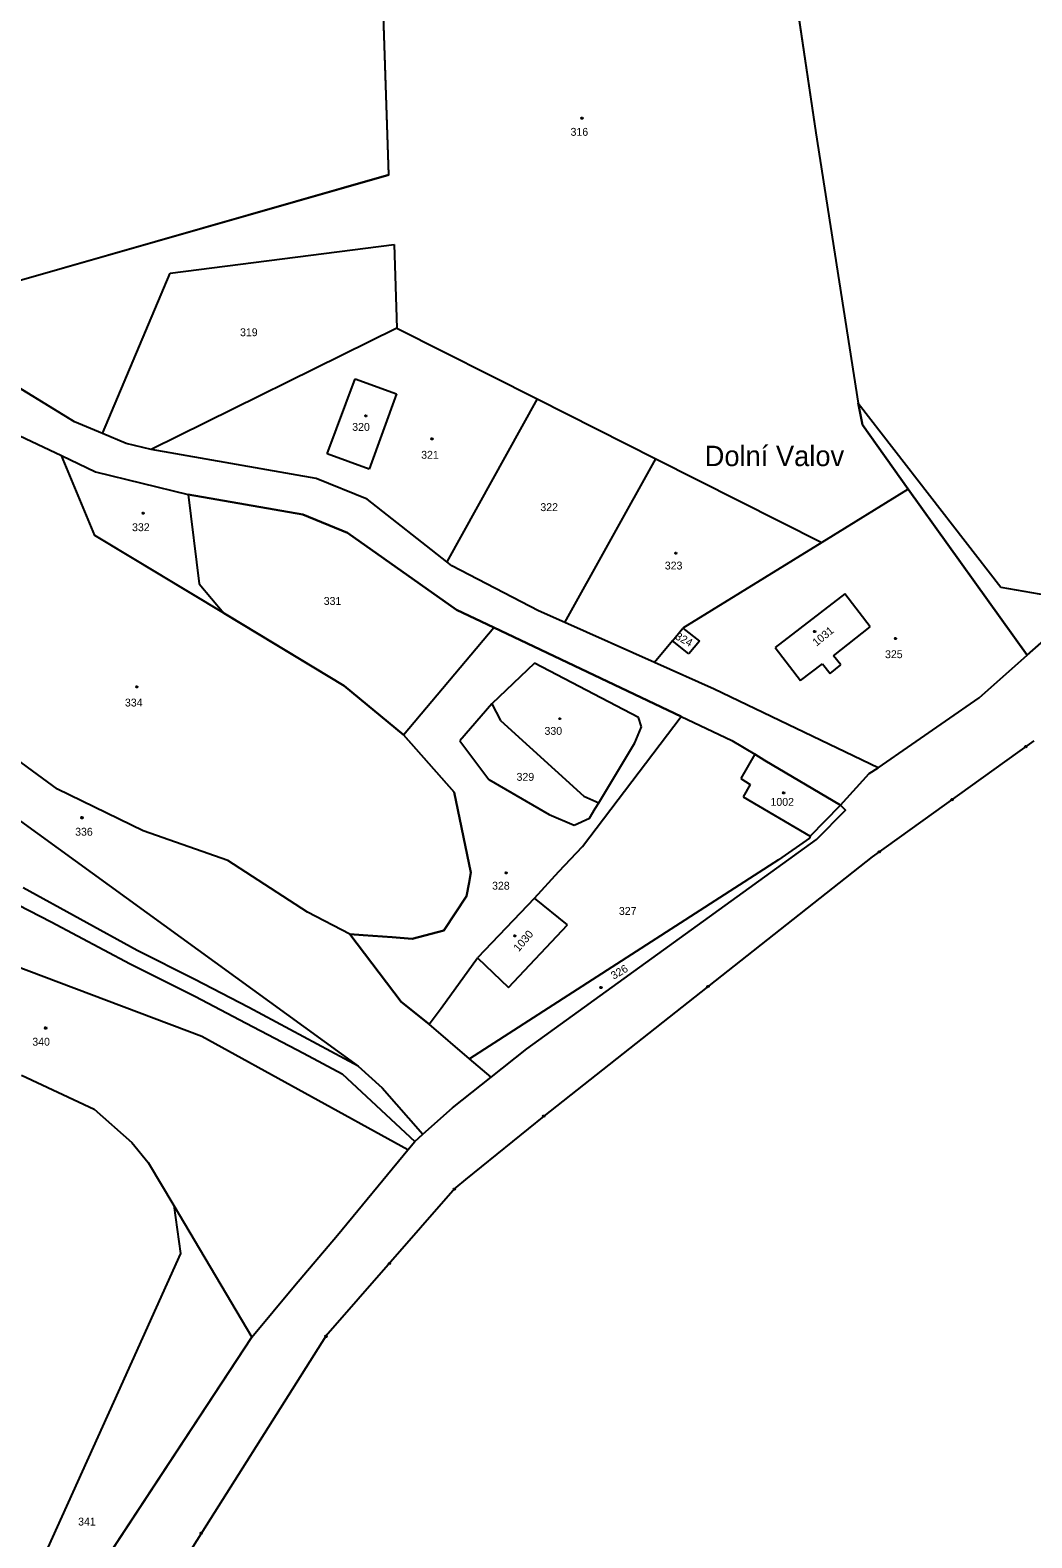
# Model space of a CAD drawing. Extents: x -841286 to -834997, y -1020681 to -1017810.
# Drawn here: x -835974.1 to -835758, y -1019779.8 to -1019454.5 of the extents above; entities that cross this region are included whole.
import ezdxf

# ---------------------------------------------------------------- set-up
doc = ezdxf.new("R2010")
doc.units = 0
for name, color, linetype in [('NERES_HRA', 7, 'Continuous'), ('NERES_SET', 7, 'Continuous'), ('OVNE_POP', 7, 'Continuous'), ('OVNE_PRE', 7, 'Continuous'), ('OVNE_SET', 7, 'Continuous'), ('OVNI_PRE', 7, 'Continuous'), ('OVNI_SET', 7, 'Continuous')]:
    doc.layers.add(name, color=color, linetype=linetype)

msp = doc.modelspace()

# ---------------------------------------------------------------- linework, layer by layer
at = {"layer": 'NERES_HRA'}
for points in [[(-835863.21, -1019688.7), (-835863.12, -1019688.85), (-835863.21, -1019689), (-835863.39, -1019689), (-835863.48, -1019688.85), (-835863.39, -1019688.7)], [(-835910.17, -1019736.18), (-835910.08, -1019736.33), (-835910.17, -1019736.48), (-835910.35, -1019736.48), (-835910.44, -1019736.33), (-835910.35, -1019736.18)]]:
    msp.add_lwpolyline(points, close=True, dxfattribs=at)
at = {"layer": 'OVNE_POP'}
for points in [[(-835854.94, -1019473.37), (-835854.85, -1019473.52), (-835854.94, -1019473.67), (-835855.12, -1019473.67), (-835855.21, -1019473.52), (-835855.12, -1019473.37)], [(-835901.59, -1019537.59), (-835901.5, -1019537.74), (-835901.59, -1019537.89), (-835901.77, -1019537.89), (-835901.86, -1019537.74), (-835901.77, -1019537.59)], [(-835887.3, -1019542.53), (-835887.21, -1019542.68), (-835887.3, -1019542.83), (-835887.48, -1019542.83), (-835887.57, -1019542.68), (-835887.48, -1019542.53)], [(-835949.6, -1019558.56), (-835949.51, -1019558.71), (-835949.6, -1019558.86), (-835949.78, -1019558.86), (-835949.87, -1019558.71), (-835949.78, -1019558.56)], [(-835834.72, -1019567.24), (-835834.63, -1019567.39), (-835834.72, -1019567.54), (-835834.9, -1019567.54), (-835834.99, -1019567.39), (-835834.9, -1019567.24)], [(-835787.3, -1019585.61), (-835787.21, -1019585.76), (-835787.3, -1019585.91), (-835787.48, -1019585.91), (-835787.57, -1019585.76), (-835787.48, -1019585.61)], [(-835950.97, -1019596.03), (-835950.88, -1019596.18), (-835950.97, -1019596.33), (-835951.15, -1019596.33), (-835951.24, -1019596.18), (-835951.15, -1019596.03)], [(-835859.76, -1019602.96), (-835859.7, -1019603.06), (-835859.76, -1019603.16), (-835859.88, -1019603.16), (-835859.94, -1019603.06), (-835859.88, -1019602.96)], [(-835962.8, -1019624.28), (-835962.71, -1019624.43), (-835962.8, -1019624.58), (-835962.98, -1019624.58), (-835963.07, -1019624.43), (-835962.98, -1019624.28)], [(-835871.3, -1019636.16), (-835871.21, -1019636.31), (-835871.3, -1019636.46), (-835871.48, -1019636.46), (-835871.57, -1019636.31), (-835871.48, -1019636.16)], [(-835850.83, -1019660.94), (-835850.74, -1019661.09), (-835850.83, -1019661.24), (-835851.01, -1019661.24), (-835851.1, -1019661.09), (-835851.01, -1019660.94)], [(-835970.66, -1019669.66), (-835970.57, -1019669.81), (-835970.66, -1019669.96), (-835970.84, -1019669.96), (-835970.93, -1019669.81), (-835970.84, -1019669.66)]]:
    msp.add_lwpolyline(points, close=True, dxfattribs=at)
at = {"layer": 'OVNE_SET'}
for p, q in [((-835817.74, -1019387.8), (-835804.58, -1019476.67)), ((-835896.74, -1019485.76), (-835899.39, -1019406.23)), ((-835804.58, -1019476.67), (-835795.47, -1019534.99)), ((-835977.44, -1019508.81), (-835896.74, -1019485.76)), ((-835943.88, -1019506.97), (-835895.58, -1019500.76)), ((-835895.58, -1019500.76), (-835895, -1019518.8)), ((-835958.47, -1019541.58), (-835943.88, -1019506.97)), ((-835895, -1019518.8), (-835947.96, -1019544.97)), ((-835895, -1019518.8), (-835864.69, -1019534.1)), ((-835964.53, -1019539.07), (-835981.95, -1019528.35)), ((-835910.04, -1019545.97), (-835903.94, -1019529.74)), ((-835903.94, -1019529.74), (-835895.08, -1019532.98)), ((-835895.08, -1019532.98), (-835900.92, -1019549.27)), ((-835864.69, -1019534.1), (-835884.22, -1019569.23)), ((-835864.69, -1019534.1), (-835839.1, -1019547.01)), ((-835795.47, -1019534.99), (-835764.7, -1019574.71)), ((-835794.55, -1019539.68), (-835795.47, -1019534.99)), ((-835958.47, -1019541.58), (-835964.53, -1019539.07)), ((-835784.65, -1019553.55), (-835794.55, -1019539.68)), ((-835977.64, -1019541.38), (-835967.33, -1019546.31)), ((-835953.39, -1019543.69), (-835958.47, -1019541.58)), ((-835947.96, -1019544.97), (-835953.39, -1019543.69)), ((-835967.33, -1019546.31), (-835959.99, -1019549.83)), ((-835960.1, -1019563.53), (-835967.33, -1019546.31)), ((-835912.4, -1019551.26), (-835947.96, -1019544.97)), ((-835900.92, -1019549.27), (-835910.04, -1019545.97)), ((-835858.73, -1019582.33), (-835839.1, -1019547.01)), ((-835839.1, -1019547.01), (-835803.32, -1019565.07)), ((-835959.99, -1019549.83), (-835939.99, -1019554.72)), ((-835901.38, -1019555.73), (-835912.4, -1019551.26)), ((-835784.65, -1019553.55), (-835803.32, -1019565.07)), ((-835759.03, -1019589.41), (-835784.65, -1019553.55)), ((-835915.29, -1019559.06), (-835939.99, -1019554.72)), ((-835939.99, -1019554.72), (-835937.6, -1019574.01)), ((-835884.22, -1019569.23), (-835901.38, -1019555.73)), ((-835905.65, -1019562.97), (-835915.29, -1019559.06)), ((-835932.3, -1019580.32), (-835960.1, -1019563.53)), ((-835882.14, -1019579.6), (-835905.65, -1019562.97)), ((-835803.32, -1019565.07), (-835833.27, -1019583.55)), ((-835883.13, -1019570.08), (-835884.22, -1019569.23)), ((-835864.4, -1019579.79), (-835883.13, -1019570.08)), ((-835937.6, -1019574.01), (-835932.3, -1019580.32)), ((-835798.32, -1019576.13), (-835813.33, -1019587.73)), ((-835792.87, -1019583.25), (-835798.32, -1019576.13)), ((-835764.7, -1019574.71), (-835751.47, -1019576.99)), ((-835874.03, -1019583.44), (-835882.14, -1019579.6)), ((-835858.73, -1019582.33), (-835864.4, -1019579.79)), ((-835932.3, -1019580.32), (-835906.31, -1019596.02)), ((-835839.37, -1019590.98), (-835858.73, -1019582.33)), ((-835759.03, -1019589.41), (-835749.9, -1019581.34)), ((-835893.57, -1019606.57), (-835874.03, -1019583.44)), ((-835833.61, -1019602.59), (-835874.03, -1019583.44)), ((-835835.52, -1019586.29), (-835839.37, -1019590.98)), ((-835835.52, -1019586.29), (-835833.27, -1019583.55)), ((-835831.98, -1019589.09), (-835835.52, -1019586.29)), ((-835833.27, -1019583.55), (-835829.72, -1019586.32)), ((-835829.72, -1019586.32), (-835831.98, -1019589.09)), ((-835800.79, -1019589.5), (-835792.87, -1019583.25)), ((-835813.33, -1019587.73), (-835807.9, -1019594.86)), ((-835799.18, -1019591.47), (-835800.79, -1019589.5)), ((-835769.38, -1019598.55), (-835759.03, -1019589.41)), ((-835865.31, -1019591.1), (-835874.46, -1019599.91)), ((-835842.84, -1019602.79), (-835865.31, -1019591.1)), ((-835826.49, -1019596.74), (-835839.37, -1019590.98)), ((-835807.9, -1019594.86), (-835803.18, -1019591.23)), ((-835803.18, -1019591.23), (-835801.53, -1019593.3)), ((-835801.53, -1019593.3), (-835799.18, -1019591.47)), ((-835906.31, -1019596.02), (-835893.57, -1019606.57)), ((-835791.12, -1019613.69), (-835826.49, -1019596.74)), ((-835791.12, -1019613.69), (-835769.38, -1019598.55)), ((-835874.46, -1019599.91), (-835881.38, -1019607.86)), ((-835874.46, -1019599.91), (-835872.59, -1019603.5)), ((-835854.9, -1019630.62), (-835833.61, -1019602.59)), ((-835833.61, -1019602.59), (-835822.69, -1019607.76)), ((-835872.59, -1019603.5), (-835854.63, -1019619.79)), ((-835843.66, -1019608.28), (-835842.2, -1019604.85)), ((-835842.2, -1019604.85), (-835842.84, -1019602.79)), ((-835968.17, -1019618.29), (-835982.57, -1019607.79)), ((-835893.57, -1019606.57), (-835882.63, -1019618.95)), ((-835881.38, -1019607.86), (-835875.16, -1019616.22)), ((-835851.43, -1019621.25), (-835843.66, -1019608.28)), ((-835822.69, -1019607.76), (-835817.76, -1019610.77)), ((-835757.56, -1019607.88), (-835761.07, -1019610.4)), ((-835817.76, -1019610.77), (-835820.78, -1019615.97)), ((-835815.62, -1019612.1), (-835817.76, -1019610.77)), ((-835799.24, -1019621.75), (-835815.62, -1019612.1)), ((-835761.07, -1019610.4), (-835789.4, -1019630.75)), ((-836032.59, -1019614.53), (-835969.54, -1019646.89)), ((-835799.24, -1019621.75), (-835793.1, -1019614.93)), ((-835793.1, -1019614.93), (-835791.12, -1019613.69)), ((-835949.72, -1019627.3), (-835968.17, -1019618.29)), ((-835875.16, -1019616.22), (-835862.14, -1019623.78)), ((-835820.78, -1019615.97), (-835818.74, -1019617.25)), ((-835818.74, -1019617.25), (-835820.26, -1019619.93)), ((-835882.63, -1019618.95), (-835879.05, -1019636.23)), ((-835854.63, -1019619.79), (-835851.43, -1019621.25)), ((-835852.16, -1019622.46), (-835851.43, -1019621.25)), ((-835820.26, -1019619.93), (-835805.81, -1019628.39)), ((-835805.81, -1019628.39), (-835799.24, -1019621.75)), ((-835798.17, -1019622.81), (-835799.24, -1019621.75)), ((-835979.84, -1019622.54), (-835903.29, -1019678.02)), ((-835862.14, -1019623.78), (-835856.71, -1019626.07)), ((-835856.71, -1019626.07), (-835853.39, -1019624.56)), ((-835853.39, -1019624.56), (-835852.16, -1019622.46)), ((-835804.47, -1019629.17), (-835798.17, -1019622.81)), ((-835931.44, -1019633.65), (-835949.72, -1019627.3)), ((-835805.81, -1019628.39), (-835805.93, -1019628.85)), ((-835866.91, -1019674.32), (-835804.47, -1019629.17)), ((-835860.04, -1019636.05), (-835854.9, -1019630.62)), ((-835805.93, -1019628.85), (-835812.63, -1019633.53)), ((-835789.4, -1019630.75), (-835792.41, -1019632.91)), ((-835937.02, -1019671.68), (-836034.19, -1019634.96)), ((-835914.23, -1019644.82), (-835931.44, -1019633.65)), ((-835812.63, -1019633.53), (-835879.3, -1019676.5)), ((-835792.41, -1019632.91), (-835863.3, -1019688.85)), ((-835879.41, -1019638.42), (-835879.97, -1019641.37)), ((-835879.05, -1019636.23), (-835879.41, -1019638.42)), ((-835865.31, -1019641.83), (-835860.04, -1019636.05)), ((-835950.97, -1019653.1), (-835975.56, -1019639.57)), ((-835879.97, -1019641.37), (-835884.86, -1019648.76)), ((-835905.13, -1019649.59), (-835914.23, -1019644.82)), ((-835865.31, -1019641.83), (-835877.6, -1019654.68)), ((-835858.17, -1019647.52), (-835865.31, -1019641.83)), ((-835969.54, -1019646.89), (-835952.52, -1019655.98)), ((-835870.87, -1019661.04), (-835858.17, -1019647.52)), ((-835902.27, -1019649.8), (-835905.13, -1019649.59)), ((-835905.13, -1019649.59), (-835894.01, -1019664.2)), ((-835896.01, -1019650.23), (-835902.27, -1019649.8)), ((-835891.69, -1019650.57), (-835896.01, -1019650.23)), ((-835884.86, -1019648.76), (-835891.69, -1019650.57)), ((-835938.68, -1019659.27), (-835950.97, -1019653.1)), ((-835885.43, -1019665.54), (-835877.6, -1019654.68)), ((-835877.6, -1019654.68), (-835870.87, -1019661.04)), ((-835952.52, -1019655.98), (-835938.58, -1019662.98)), ((-835926.94, -1019665.41), (-835938.68, -1019659.27)), ((-835938.58, -1019662.98), (-835927.47, -1019668.75)), ((-835894.01, -1019664.2), (-835887.99, -1019668.99)), ((-835903.29, -1019678.02), (-835926.94, -1019665.41)), ((-835887.99, -1019668.99), (-835885.43, -1019665.54)), ((-835927.47, -1019668.75), (-835915.08, -1019675.23)), ((-835879.3, -1019676.5), (-835887.99, -1019668.99)), ((-835892.58, -1019696.11), (-835937.02, -1019671.68)), ((-835915.08, -1019675.23), (-835906.79, -1019679.73)), ((-835874.65, -1019680.44), (-835879.3, -1019676.5)), ((-835874.65, -1019680.44), (-835866.91, -1019674.32)), ((-835975.95, -1019680.01), (-835960.3, -1019687.33)), ((-835906.79, -1019679.73), (-835891.11, -1019694.32)), ((-835903.29, -1019678.02), (-835898.17, -1019682.74)), ((-835882.99, -1019687.04), (-835874.65, -1019680.44)), ((-835898.17, -1019682.74), (-835889.36, -1019692.75)), ((-835889.36, -1019692.75), (-835882.99, -1019687.04)), ((-835960.3, -1019687.33), (-835952.11, -1019694.55)), ((-835863.3, -1019688.85), (-835880.19, -1019702.53)), ((-835891.11, -1019694.32), (-835889.36, -1019692.75)), ((-835952.11, -1019694.55), (-835948.6, -1019698.84)), ((-835907.76, -1019714.51), (-835892.58, -1019696.11)), ((-835892.58, -1019696.11), (-835891.11, -1019694.32)), ((-835948.6, -1019698.84), (-835943.1, -1019708.11)), ((-835880.19, -1019702.53), (-835882.26, -1019704.2)), ((-835882.93, -1019704.97), (-835910.26, -1019736.33)), ((-835882.26, -1019704.2), (-835882.93, -1019704.97)), ((-835943.1, -1019708.11), (-835941.62, -1019718.43)), ((-835943.1, -1019708.11), (-835926.23, -1019736.52)), ((-835917.06, -1019725.44), (-835907.76, -1019714.51)), ((-835941.62, -1019718.43), (-835955.07, -1019748.33)), ((-835926.23, -1019736.52), (-835917.06, -1019725.44)), ((-835972.16, -1019806.36), (-835926.23, -1019736.52)), ((-835910.26, -1019736.33), (-835964.1, -1019821.36)), ((-835955.07, -1019748.33), (-835972.62, -1019787.16))]:
    msp.add_line(p, q, dxfattribs=at)
for points in [[(-835759.3, -1019609.31), (-835759.46, -1019609.24), (-835759.48, -1019609.07), (-835759.33, -1019608.97), (-835759.17, -1019609.04), (-835759.15, -1019609.21)], [(-835775.22, -1019620.75), (-835775.38, -1019620.68), (-835775.4, -1019620.51), (-835775.25, -1019620.4), (-835775.09, -1019620.47), (-835775.07, -1019620.64)], [(-835790.89, -1019632), (-835791.05, -1019631.93), (-835791.07, -1019631.76), (-835790.92, -1019631.66), (-835790.76, -1019631.73), (-835790.74, -1019631.9)], [(-835827.83, -1019661.05), (-835828, -1019660.99), (-835828.02, -1019660.82), (-835827.88, -1019660.71), (-835827.71, -1019660.77), (-835827.69, -1019660.94)], [(-835882.54, -1019704.75), (-835882.71, -1019704.72), (-835882.77, -1019704.55), (-835882.65, -1019704.42), (-835882.48, -1019704.45), (-835882.42, -1019704.62)], [(-835896.54, -1019720.82), (-835896.71, -1019720.79), (-835896.77, -1019720.62), (-835896.65, -1019720.48), (-835896.48, -1019720.51), (-835896.42, -1019720.68)], [(-835937.1, -1019779), (-835937.28, -1019779), (-835937.35, -1019778.84), (-835937.26, -1019778.69), (-835937.08, -1019778.69), (-835937.01, -1019778.85)]]:
    msp.add_lwpolyline(points, close=True, dxfattribs=at)
at = {"layer": 'OVNI_PRE'}
for points in [[(-835804.75, -1019584.09), (-835804.66, -1019584.24), (-835804.75, -1019584.39), (-835804.93, -1019584.39), (-835805.02, -1019584.24), (-835804.93, -1019584.09)], [(-835811.45, -1019618.94), (-835811.36, -1019619.09), (-835811.45, -1019619.24), (-835811.63, -1019619.24), (-835811.72, -1019619.09), (-835811.63, -1019618.94)], [(-835869.43, -1019649.78), (-835869.34, -1019649.93), (-835869.43, -1019650.08), (-835869.61, -1019650.08), (-835869.7, -1019649.93), (-835869.61, -1019649.78)]]:
    msp.add_lwpolyline(points, close=True, dxfattribs=at)
at = {"layer": 'OVNI_SET'}
for points in [[(-835817.74, -1019387.8), (-835804.58, -1019476.67), (-835795.47, -1019534.99), (-835794.55, -1019539.68), (-835784.65, -1019553.55), (-835759.03, -1019589.41), (-835749.9, -1019581.34)], [(-835977.44, -1019508.81), (-835896.74, -1019485.7), (-835899.39, -1019406.23)], [(-835972.16, -1019806.36), (-835926.23, -1019736.52), (-835917.06, -1019725.44), (-835907.76, -1019714.51), (-835892.58, -1019696.11), (-835891.11, -1019694.32), (-835889.36, -1019692.75), (-835882.99, -1019687.04), (-835874.65, -1019680.44), (-835879.3, -1019676.5), (-835887.99, -1019668.99), (-835894.01, -1019664.2), (-835905.13, -1019649.59), (-835902.27, -1019649.8), (-835896.01, -1019650.23), (-835891.69, -1019650.57), (-835884.86, -1019648.76), (-835879.97, -1019641.37), (-835879.41, -1019638.42), (-835879.05, -1019636.23), (-835882.63, -1019618.95), (-835893.57, -1019606.57), (-835906.31, -1019596.02), (-835931.1, -1019581.05), (-835960.1, -1019563.53), (-835967.33, -1019546.31), (-835959.99, -1019549.83), (-835939.99, -1019554.72), (-835915.29, -1019559.06), (-835905.65, -1019562.97), (-835882.14, -1019579.6), (-835874.03, -1019583.44), (-835833.61, -1019602.59), (-835822.69, -1019607.76), (-835817.76, -1019610.77), (-835815.62, -1019612.1), (-835799.24, -1019621.75), (-835793.1, -1019614.93), (-835791.12, -1019613.69), (-835826.49, -1019596.74), (-835839.37, -1019590.98), (-835858.73, -1019582.33), (-835864.4, -1019579.79), (-835883.13, -1019570.08), (-835884.22, -1019569.23), (-835901.38, -1019555.73), (-835912.4, -1019551.26), (-835947.96, -1019544.97), (-835953.39, -1019543.69), (-835958.47, -1019541.58), (-835964.53, -1019539.07), (-835981.95, -1019528.35)], [(-835791.12, -1019613.69), (-835769.38, -1019598.55), (-835759.03, -1019589.41)], [(-835874.65, -1019680.44), (-835866.91, -1019674.32), (-835804.47, -1019629.17), (-835798.17, -1019622.81), (-835799.24, -1019621.75)]]:
    msp.add_lwpolyline(points, dxfattribs=at)

# ---------------------------------------------------------------- texts
at = {"layer": 'NERES_SET'}
msp.add_text('Dolní Valov', height=4.4, dxfattribs=at).set_placement((-835828.57, -1019548.59))
at = {"layer": 'OVNE_PRE'}
for s, p in [('316', (-835857.5, -1019477.32)), ('319', (-835928.8, -1019520.56)), ('320', (-835904.6, -1019540.98)), ('321', (-835889.73, -1019547)), ('322', (-835864.01, -1019558.29)), ('332', (-835952.09, -1019562.62)), ('323', (-835837.17, -1019570.89)), ('331', (-835910.75, -1019578.53)), ('325', (-835789.66, -1019590.02)), ('334', (-835953.63, -1019600.45)), ('330', (-835863.12, -1019606.56)), ('329', (-835869.15, -1019616.48)), ('1002', (-835814.37, -1019621.88)), ('336', (-835964.37, -1019628.32)), ('328', (-835874.43, -1019639.96)), ('327', (-835847.07, -1019645.41)), ('340', (-835973.61, -1019673.62)), ('341', (-835963.73, -1019777.16))]:
    msp.add_text(s, height=1.7, dxfattribs=at).set_placement(p)
for s, rotation, p in [('324', 331.3988, (-835835.09, -1019585.81)), ('1031', 39.5914, (-835804.44, -1019587.56)), ('1030', 49.5036, (-835868.69, -1019653.49)), ('326', 30.7678, (-835848.19, -1019659.42))]:
    msp.add_text(s, height=1.7, rotation=rotation, dxfattribs=at).set_placement(p)

doc.saveas('drawing.dxf')
